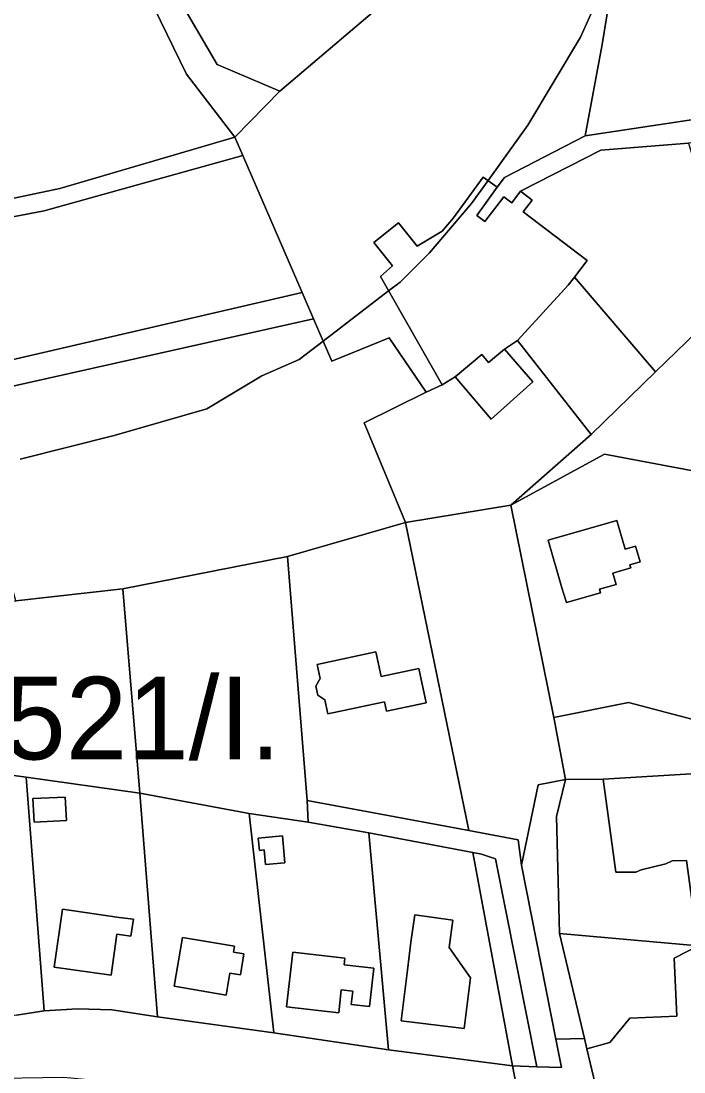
# Model space of a CAD drawing. Extents: x -477304 to -465429, y -1159113 to -1149210.
# Drawn here: x -473327.8 to -473207.5, y -1153799.6 to -1153608.7 of the extents above; entities that cross this region are included whole.
import ezdxf

# ---------------------------------------------------------------- set-up
doc = ezdxf.new("R2010")
doc.units = 0
for name, color, linetype in [('BPEJ_s', 7, 'Continuous'), ('ostatni_s', 7, 'Continuous'), ('sad_s', 7, 'Continuous'), ('trav_porost_s', 7, 'Continuous'), ('zahrada_s', 7, 'Continuous')]:
    doc.layers.add(name, color=color, linetype=linetype)

msp = doc.modelspace()

# ---------------------------------------------------------------- linework, layer by layer
at = {"layer": 'BPEJ_s'}
for points in [[(-473327.92, -1153688.29), (-473310.9, -1153684.03), (-473294.09, -1153679.14), (-473284.09, -1153673.18), (-473277.28, -1153670.2), (-473272.93, -1153666.86), (-473261.06, -1153657.75), (-473258.98, -1153656.16), (-473253.66, -1153650.84), (-473246, -1153641.9), (-473243, -1153637.72), (-473235.79, -1153627.64), (-473226.21, -1153611.68), (-473219.73, -1153597.09)], [(-473219.73, -1153597.09), (-473226.21, -1153611.68), (-473235.79, -1153627.64), (-473243, -1153637.72), (-473246, -1153641.9), (-473253.66, -1153650.84), (-473258.98, -1153656.16), (-473261.06, -1153657.75), (-473272.93, -1153666.86), (-473277.28, -1153670.2), (-473284.09, -1153673.18), (-473294.09, -1153679.14), (-473310.9, -1153684.03), (-473327.92, -1153688.29)]]:
    msp.add_lwpolyline(points, dxfattribs=at)
at = {"layer": 'ostatni_s'}
for points in [[(-473192.34, -1153628.79), (-473206.66, -1153630.9), (-473222.53, -1153632.18), (-473237.11, -1153639.64), (-473238.73, -1153641.76), (-473240.16, -1153640.66), (-473243.6, -1153645.15), (-473245.05, -1153644.04), (-473241.35, -1153638.91), (-473240.01, -1153637.13), (-473225.37, -1153629.58), (-473165.99, -1153620.61), (-473166, -1153624.91)], [(-473237.69, -1153666.74), (-473240.03, -1153668.31), (-473242.93, -1153670.72), (-473244.13, -1153669.29), (-473248.99, -1153673.38), (-473251.34, -1153674.79), (-473262.56, -1153655.13), (-473260.37, -1153653.21), (-473263.76, -1153648.97), (-473259.3, -1153645.41), (-473255.91, -1153649.65), (-473251.34, -1153646.87), (-473249.26, -1153644.49), (-473243.9, -1153637.07), (-473241.35, -1153638.91), (-473245.05, -1153644.04), (-473243.6, -1153645.15), (-473240.16, -1153640.66), (-473238.73, -1153641.76), (-473237.11, -1153639.64), (-473235.01, -1153641.25), (-473236.64, -1153643.36), (-473225.03, -1153652.24), (-473227.31, -1153655.22), (-473228.47, -1153656.73)], [(-473242.47, -1153681.06), (-473248.99, -1153673.38), (-473244.13, -1153669.29), (-473242.93, -1153670.72), (-473240.03, -1153668.31), (-473234.9, -1153674.25)], [(-473218.11, -1153704.67), (-473216.24, -1153704.13), (-473215.42, -1153706.96), (-473217.29, -1153707.51), (-473217.13, -1153708.06), (-473220.36, -1153708.99), (-473219.79, -1153711.05), (-473222.79, -1153711.91), (-473222.6, -1153712.57), (-473228.8, -1153714.31), (-473229.62, -1153711.67), (-473232.11, -1153703.02), (-473219.63, -1153699.42)], [(-473263.37, -1153723.31), (-473262.39, -1153727.77), (-473255.61, -1153726.33), (-473254.24, -1153732.56), (-473261.44, -1153734.08), (-473261.8, -1153732.37), (-473272.09, -1153734.55), (-473272.63, -1153732.02), (-473273.93, -1153731.15), (-473274.29, -1153729.53), (-473273.5, -1153728.11), (-473274.04, -1153725.58)], [(-473192.11, -1153744.58), (-473192.03, -1153746.16), (-473191.72, -1153749.97), (-473191.09, -1153756.05), (-473189.73, -1153769.69), (-473199.98, -1153770.71), (-473196.68, -1153778.59), (-473204.89, -1153776.67), (-473207.01, -1153761.18), (-473209.57, -1153761.24), (-473210.72, -1153761.78), (-473215.2, -1153762.9), (-473216.2, -1153763.29), (-473219.85, -1153763.34), (-473222.14, -1153746.41)], [(-473319.55, -1153753.92), (-473325.43, -1153754.21), (-473325.64, -1153749.96), (-473319.76, -1153749.67)], [(-473279.91, -1153761.59), (-473283.44, -1153761.91), (-473283.68, -1153759.27), (-473284.53, -1153759.35), (-473284.73, -1153757.13), (-473280.35, -1153756.73)], [(-473309.99, -1153771.52), (-473307.4, -1153771.86), (-473307.83, -1153774.93), (-473310.43, -1153774.58), (-473311.41, -1153782.02), (-473321.77, -1153780.56), (-473320.29, -1153770.06)], [(-473249.38, -1153772), (-473250.08, -1153777.01), (-473246.23, -1153782.52), (-473247.36, -1153791.72), (-473258.8, -1153790.31), (-473257.66, -1153781.11), (-473257.01, -1153776.04), (-473256.31, -1153771.03)], [(-473225.52, -1153793.53), (-473230.06, -1153774.46), (-473204.89, -1153776.67), (-473209.21, -1153778.95), (-473208.75, -1153789.48), (-473217.28, -1153789.85), (-473220.91, -1153794.27), (-473225.08, -1153795.41)], [(-473289.24, -1153777.81), (-473287.32, -1153778.13), (-473287.94, -1153781.96), (-473289.86, -1153781.64), (-473290.54, -1153785.65), (-473300.01, -1153784.04), (-473298.5, -1153775.17), (-473289.07, -1153776.77)], [(-473264.56, -1153787.73), (-473267.84, -1153787.35), (-473267.56, -1153784.91), (-473269.66, -1153784.67), (-473270.08, -1153788.87), (-473279.61, -1153787.77), (-473278.46, -1153777.84), (-473269.01, -1153778.93), (-473269.14, -1153780.12), (-473267.04, -1153780.36), (-473263.76, -1153780.73)], [(-473237.51, -1153804.1), (-473238.56, -1153798.46), (-473234.18, -1153798.69), (-473229.71, -1153798.76), (-473230.72, -1153793.62), (-473225.52, -1153793.53), (-473225.08, -1153795.41), (-473222.61, -1153805.8)]]:
    msp.add_lwpolyline(points, close=True, dxfattribs=at)
msp.add_lwpolyline([(-473328.63, -1153789.29), (-473323.57, -1153788.52), (-473317.53, -1153788.14), (-473311.33, -1153788.34), (-473303, -1153789.58), (-473281.9, -1153792.51), (-473261.1, -1153795.57), (-473238.56, -1153798.46), (-473237.51, -1153804.1), (-473222.61, -1153805.8), (-473208.25, -1153807.17), (-473209.21, -1153812.76), (-473217.53, -1153812.07), (-473213.4, -1153816.66), (-473218.18, -1153816.11), (-473221.95, -1153807.89), (-473233.42, -1153811.73), (-473238.9, -1153813.1), (-473239.78, -1153809.33), (-473288.05, -1153803.68), (-473320, -1153800.62), (-473335.25, -1153800.87)], dxfattribs=at)
at = {"layer": 'sad_s'}
msp.add_lwpolyline([(-473219.28, -1153594.33), (-473222.31, -1153613.01), (-473225.37, -1153629.58), (-473240.01, -1153637.13), (-473241.35, -1153638.91), (-473243.9, -1153637.07), (-473249.26, -1153644.49), (-473251.34, -1153646.87), (-473255.91, -1153649.65), (-473259.3, -1153645.41), (-473263.76, -1153648.97), (-473260.37, -1153653.21), (-473262.56, -1153655.13), (-473251.34, -1153674.79), (-473254.24, -1153676.15), (-473260.99, -1153666.26), (-473271.36, -1153670.48), (-473274.69, -1153662.8), (-473276.76, -1153658.02), (-473287.54, -1153633.17), (-473289, -1153629.8), (-473280.84, -1153621.45), (-473258.82, -1153602.79)], dxfattribs=at)
at = {"layer": 'trav_porost_s'}
for points in [[(-473261.86, -1153559.8), (-473265.09, -1153577.49), (-473250.8, -1153583.47), (-473258.82, -1153602.79), (-473280.84, -1153621.45), (-473292.21, -1153616.61), (-473303.42, -1153597.29), (-473308.02, -1153574.98), (-473295, -1153574.28)], [(-473177.24, -1153606.57), (-473183.9, -1153607.02), (-473182.33, -1153618.65), (-473165.99, -1153620.61), (-473225.37, -1153629.58), (-473222.31, -1153613.01), (-473219.28, -1153594.33), (-473215.7, -1153572.32), (-473215.63, -1153571.87), (-473213.13, -1153572.08), (-473207.97, -1153572.41), (-473174.84, -1153574.79)], [(-473320.73, -1153639.17), (-473359.53, -1153647.3), (-473360.09, -1153645.69), (-473377.78, -1153590.09), (-473360.31, -1153585.83), (-473358.01, -1153593.19), (-473344.19, -1153589.79), (-473345.22, -1153586.76), (-473325.94, -1153576.44), (-473312.01, -1153575.23), (-473307.17, -1153598.94), (-473297.77, -1153618.39), (-473289, -1153629.8)], [(-473312.01, -1153575.23), (-473308.02, -1153574.98), (-473303.42, -1153597.29), (-473292.21, -1153616.61), (-473280.84, -1153621.45), (-473289, -1153629.8), (-473297.77, -1153618.39), (-473307.17, -1153598.94)], [(-473323.61, -1153643.18), (-473359.06, -1153650.01), (-473359.53, -1153647.3), (-473320.73, -1153639.17), (-473289, -1153629.8), (-473287.54, -1153633.17)], [(-473236.64, -1153643.36), (-473235.01, -1153641.25), (-473237.11, -1153639.64), (-473222.53, -1153632.18), (-473206.66, -1153630.9), (-473198.32, -1153658.67), (-473198.17, -1153659.18), (-473201.58, -1153662.13), (-473205.1, -1153665.16), (-473212.62, -1153672.46), (-473227.31, -1153655.22), (-473225.03, -1153652.24)], [(-473287.54, -1153633.17), (-473276.76, -1153658.02), (-473348.05, -1153674.58), (-473359.06, -1153650.01), (-473323.61, -1153643.18)], [(-473227.31, -1153655.22), (-473212.62, -1153672.46), (-473224.31, -1153683.81), (-473237.69, -1153666.74), (-473228.47, -1153656.73)], [(-473348.05, -1153674.58), (-473276.76, -1153658.02), (-473274.69, -1153662.8), (-473346.66, -1153678.95)], [(-473271.36, -1153670.48), (-473260.99, -1153666.26), (-473254.24, -1153676.15), (-473265.49, -1153681.73), (-473258.02, -1153699.83), (-473279.44, -1153706), (-473309.32, -1153711.87), (-473328.74, -1153714.06), (-473336.43, -1153685.68), (-473344.02, -1153687.21), (-473346.66, -1153678.95), (-473274.69, -1153662.8)], [(-473189.58, -1153688.83), (-473189.39, -1153701.74), (-473192.63, -1153692.92), (-473221.86, -1153687.37), (-473238.91, -1153696.67), (-473224.31, -1153683.81), (-473212.62, -1153672.46), (-473205.1, -1153665.16), (-473202.86, -1153677.29), (-473202.42, -1153679.72), (-473190.83, -1153679.34), (-473189.45, -1153683.05), (-473189.43, -1153684.55), (-473191.63, -1153684.58), (-473191.57, -1153688.85)], [(-473189.39, -1153701.74), (-473189.34, -1153705.39), (-473192.02, -1153705.48), (-473194.2, -1153731.34), (-473201.45, -1153736.76), (-473217.55, -1153732.5), (-473231.05, -1153735.2), (-473238.91, -1153696.67), (-473221.86, -1153687.37), (-473192.63, -1153692.92)], [(-473231.05, -1153735.2), (-473228.94, -1153746.48), (-473233.91, -1153747.44), (-473236.95, -1153762.03), (-473237.54, -1153757.45), (-473246.5, -1153755.77), (-473258.02, -1153699.83), (-473238.91, -1153696.67)], [(-473275.84, -1153750.27), (-473279.44, -1153706), (-473258.02, -1153699.83), (-473246.5, -1153755.77)], [(-473217.29, -1153707.51), (-473215.42, -1153706.96), (-473216.24, -1153704.13), (-473218.11, -1153704.67), (-473219.63, -1153699.42), (-473232.11, -1153703.02), (-473229.62, -1153711.67), (-473228.8, -1153714.31), (-473222.6, -1153712.57), (-473222.79, -1153711.91), (-473219.79, -1153711.05), (-473220.36, -1153708.99), (-473217.13, -1153708.06)], [(-473306.24, -1153748.96), (-473309.32, -1153711.87), (-473279.44, -1153706), (-473275.84, -1153750.27), (-473275.64, -1153754.24), (-473286.38, -1153752.68)], [(-473367.48, -1153757.98), (-473373.05, -1153760.17), (-473369, -1153733.53), (-473367.79, -1153717.35), (-473336.16, -1153714.92), (-473328.74, -1153714.06), (-473309.32, -1153711.87), (-473306.24, -1153748.96), (-473326.84, -1153746.03), (-473339.48, -1153744.35), (-473347.35, -1153749.68)], [(-473274.04, -1153725.58), (-473273.5, -1153728.11), (-473274.29, -1153729.53), (-473273.93, -1153731.15), (-473272.63, -1153732.02), (-473272.09, -1153734.55), (-473261.8, -1153732.37), (-473261.44, -1153734.08), (-473254.24, -1153732.56), (-473255.61, -1153726.33), (-473262.39, -1153727.77), (-473263.37, -1153723.31)], [(-473231.05, -1153735.2), (-473217.55, -1153732.5), (-473201.45, -1153736.76), (-473194.2, -1153731.34), (-473193.85, -1153736.82), (-473192.11, -1153744.58), (-473222.14, -1153746.41), (-473228.94, -1153746.48)], [(-473339.06, -1153790.93), (-473342.5, -1153792.45), (-473347.35, -1153749.68), (-473339.48, -1153744.35), (-473326.84, -1153746.03), (-473323.57, -1153788.52), (-473328.63, -1153789.29)], [(-473317.53, -1153788.14), (-473323.57, -1153788.52), (-473326.84, -1153746.03), (-473306.24, -1153748.96), (-473303, -1153789.58), (-473311.33, -1153788.34)], [(-473230.59, -1153753.2), (-473230.06, -1153774.46), (-473225.52, -1153793.53), (-473230.72, -1153793.62), (-473236.95, -1153762.03), (-473233.91, -1153747.44), (-473228.94, -1153746.48)], [(-473325.64, -1153749.96), (-473325.43, -1153754.21), (-473319.55, -1153753.92), (-473319.76, -1153749.67)], [(-473234.18, -1153798.69), (-473241.66, -1153760.87), (-473244.19, -1153760.05), (-473245.81, -1153759.74), (-473264.63, -1153756.17), (-473275.64, -1153754.24), (-473275.84, -1153750.27), (-473246.5, -1153755.77), (-473237.54, -1153757.45), (-473236.95, -1153762.03), (-473230.72, -1153793.62), (-473229.71, -1153798.76)], [(-473261.1, -1153795.57), (-473281.9, -1153792.51), (-473286.38, -1153752.68), (-473275.64, -1153754.24), (-473264.63, -1153756.17)], [(-473284.73, -1153757.13), (-473284.53, -1153759.35), (-473283.68, -1153759.27), (-473283.44, -1153761.91), (-473279.91, -1153761.59), (-473280.35, -1153756.73)], [(-473261.1, -1153795.57), (-473264.63, -1153756.17), (-473245.81, -1153759.74), (-473238.56, -1153798.46)], [(-473244.19, -1153760.05), (-473241.66, -1153760.87), (-473234.18, -1153798.69), (-473238.56, -1153798.46), (-473245.81, -1153759.74)], [(-473307.83, -1153774.93), (-473307.4, -1153771.86), (-473309.99, -1153771.52), (-473320.29, -1153770.06), (-473321.77, -1153780.56), (-473311.41, -1153782.02), (-473310.43, -1153774.58)], [(-473247.36, -1153791.72), (-473246.23, -1153782.52), (-473250.08, -1153777.01), (-473249.38, -1153772), (-473256.31, -1153771.03), (-473257.01, -1153776.04), (-473257.66, -1153781.11), (-473258.8, -1153790.31)], [(-473270.08, -1153788.87), (-473269.66, -1153784.67), (-473267.56, -1153784.91), (-473267.84, -1153787.35), (-473264.56, -1153787.73), (-473263.76, -1153780.73), (-473267.04, -1153780.36), (-473269.14, -1153780.12), (-473269.01, -1153778.93), (-473278.46, -1153777.84), (-473279.61, -1153787.77)]]:
    msp.add_lwpolyline(points, close=True, dxfattribs=at)
at = {"layer": 'zahrada_s'}
for points in [[(-473238.91, -1153696.67), (-473258.02, -1153699.83), (-473265.49, -1153681.73), (-473254.24, -1153676.15), (-473251.34, -1153674.79), (-473248.99, -1153673.38), (-473242.47, -1153681.06), (-473234.9, -1153674.25), (-473240.03, -1153668.31), (-473237.69, -1153666.74), (-473224.31, -1153683.81)], [(-473215.2, -1153762.9), (-473210.72, -1153761.78), (-473209.57, -1153761.24), (-473207.01, -1153761.18), (-473204.89, -1153776.67), (-473230.06, -1153774.46), (-473230.59, -1153753.2), (-473228.94, -1153746.48), (-473222.14, -1153746.41), (-473219.85, -1153763.34), (-473216.2, -1153763.29)], [(-473286.38, -1153752.68), (-473281.9, -1153792.51), (-473303, -1153789.58), (-473306.24, -1153748.96)], [(-473289.86, -1153781.64), (-473287.94, -1153781.96), (-473287.32, -1153778.13), (-473289.24, -1153777.81), (-473289.07, -1153776.77), (-473298.5, -1153775.17), (-473300.01, -1153784.04), (-473290.54, -1153785.65)], [(-473220.91, -1153794.27), (-473217.28, -1153789.85), (-473208.75, -1153789.48), (-473209.21, -1153778.95), (-473204.89, -1153776.67), (-473203.65, -1153780.7), (-473194.37, -1153787.35), (-473169.12, -1153801.95), (-473166.41, -1153804.46), (-473166.65, -1153806.23), (-473202.85, -1153783.66), (-473195.4, -1153808.43), (-473208.25, -1153807.17), (-473222.61, -1153805.8), (-473225.08, -1153795.41)]]:
    msp.add_lwpolyline(points, close=True, dxfattribs=at)

# ---------------------------------------------------------------- texts
at = {"layer": 'BPEJ_s'}
msp.add_text('83521/I.', height=15, dxfattribs=at).set_placement((-473353.13, -1153742.83))

doc.saveas('drawing.dxf')
